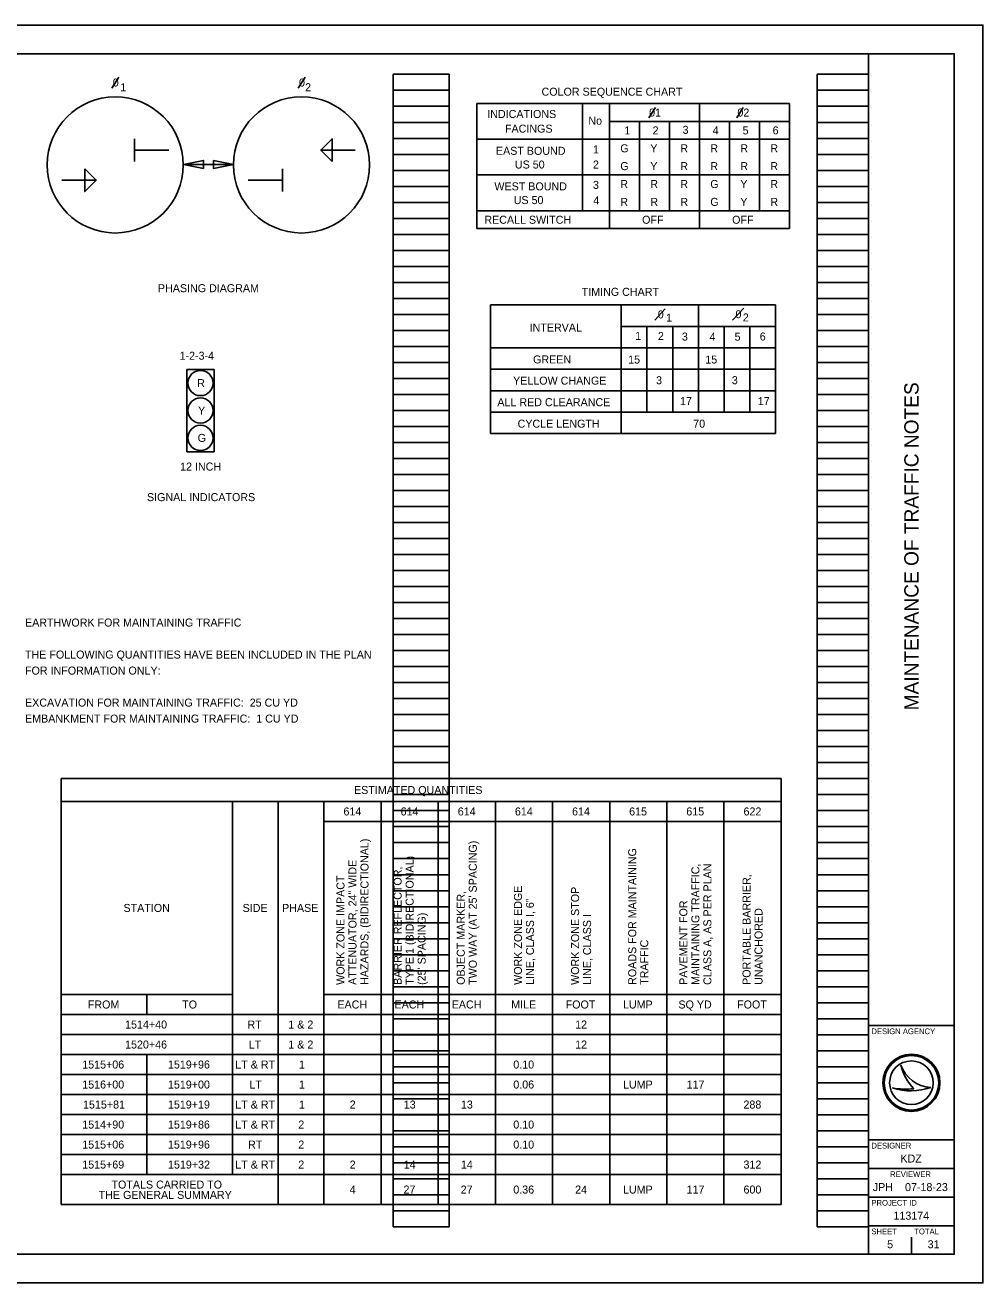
# Model space of a CAD drawing. Extents: x 0 to 34, y 0 to 22.
# Drawn here: x 17.24 to 34, y 0 to 22 of the extents above; entities that cross this region are included whole.
import ezdxf

# ---------------------------------------------------------------- set-up
doc = ezdxf.new("R2010")
doc.units = 0
for name, color, linetype in [('Default', 7, 'Continuous'), ('SG_P_Heads', 7, 'Continuous'), ('SH_Border', 7, 'Continuous'), ('SH_Cut_Line', 7, 'Continuous'), ('SH_Data', 7, 'Continuous'), ('SH_Text', 7, 'Continuous'), ('TX_P_1', 7, 'Continuous'), ('TX_P_20', 7, 'Continuous')]:
    doc.layers.add(name, color=color, linetype=linetype)

msp = doc.modelspace()

# ---------------------------------------------------------------- linework, layer by layer
at = {"layer": 'Default'}
for p, q in [((25.145, 20.629), (25.145, 18.441)), ((25.145, 20.629), (30.615, 20.629)), ((26.996, 20.629), (26.996, 18.754)), ((27.465, 20.629), (27.465, 18.441)), ((29.04, 20.629), (29.04, 18.441)), ((30.615, 20.629), (30.615, 18.441)), ((30.615, 20.629), (30.615, 18.441)), ((27.465, 20.316), (30.615, 20.316)), ((27.99, 20.316), (27.99, 18.754)), ((28.515, 20.316), (28.515, 18.754)), ((29.565, 20.316), (29.565, 18.754)), ((30.09, 20.316), (30.09, 18.754)), ((25.145, 20.004), (30.615, 20.004)), ((25.145, 19.379), (30.615, 19.379)), ((25.145, 18.754), (30.615, 18.754)), ((25.145, 18.441), (30.615, 18.441)), ((25.387, 17.106), (30.373, 17.106)), ((25.387, 17.106), (25.387, 14.856)), ((27.673, 17.106), (27.673, 14.856)), ((29.023, 17.106), (29.023, 15.231)), ((30.373, 17.106), (30.373, 14.856)), ((27.673, 16.731), (30.373, 16.731)), ((28.123, 16.731), (28.123, 15.231)), ((28.573, 16.731), (28.573, 15.231)), ((29.473, 16.731), (29.473, 15.231)), ((29.923, 16.731), (29.923, 15.231)), ((25.387, 16.356), (30.373, 16.356)), ((20.55, 15.976), (20.071, 15.976)), ((20.071, 15.976), (20.071, 14.534)), ((20.55, 14.534), (20.55, 15.976)), ((25.387, 15.981), (30.373, 15.981)), ((25.387, 15.606), (30.373, 15.606)), ((25.387, 15.231), (30.373, 15.231)), ((25.387, 14.856), (30.373, 14.856)), ((20.071, 14.534), (20.55, 14.534))]:
    msp.add_line(p, q, dxfattribs=at)
for centre in [(20.31, 15.739), (20.31, 15.259), (20.31, 14.78)]:
    msp.add_circle(centre, 0.22, dxfattribs=at)
at = {"layer": 'SG_P_Heads'}
for p, q in [((19.154, 20.014), (19.154, 19.614)), ((19.755, 19.814), (19.154, 19.814)), ((23.014, 19.814), (22.414, 19.814)), ((21.744, 19.089), (21.744, 19.489)), ((17.884, 19.289), (18.485, 19.289)), ((21.143, 19.289), (21.744, 19.289))]:
    msp.add_line(p, q, dxfattribs=at)
for points in [[(22.614, 19.614), (22.414, 19.814), (22.614, 20.014)], [(20.362, 19.493), (20.012, 19.563), (20.362, 19.633)], [(20.535, 19.633), (20.885, 19.563), (20.535, 19.493)], [(18.285, 19.489), (18.485, 19.289), (18.285, 19.089)]]:
    msp.add_lwpolyline(points, close=True, dxfattribs=at)
at = {"layer": 'SH_Border'}
for p, q in [((32, 0.5), (32, 21.5)), ((32, 4.5), (33.5, 4.5)), ((32, 2.5), (33.5, 2.5)), ((32, 2), (33.5, 2)), ((32, 1.5), (33.5, 1.5)), ((32, 1), (33.5, 1))]:
    msp.add_line(p, q, dxfattribs=at)
msp.add_lwpolyline([(1.5, 21.5), (33.5, 21.5), (33.5, 0.5), (1.5, 0.5)], close=True, dxfattribs=at)
at = {"layer": 'SH_Cut_Line'}
msp.add_lwpolyline([(0, 0), (34, 0), (34, 22), (0, 22)], close=True, dxfattribs=at)
at = {"layer": 'SH_Data'}
for p, q in [((23.68, 0.98), (23.68, 21.14)), ((23.68, 21.14), (24.66, 21.14)), ((24.66, 0.98), (24.66, 21.14)), ((31.1, 0.98), (31.1, 21.14)), ((31.1, 21.14), (32, 21.14)), ((32, 0.98), (32, 21.14)), ((23.68, 20.86), (24.66, 20.86)), ((31.1, 20.86), (32, 20.86)), ((23.68, 20.58), (24.66, 20.58)), ((31.1, 20.58), (32, 20.58)), ((23.68, 20.3), (24.66, 20.3)), ((31.1, 20.3), (32, 20.3)), ((23.68, 20.02), (24.66, 20.02)), ((31.1, 20.02), (32, 20.02)), ((23.68, 19.74), (24.66, 19.74)), ((31.1, 19.74), (32, 19.74)), ((20.885, 19.563), (20.012, 19.563)), ((23.68, 19.46), (24.66, 19.46)), ((31.1, 19.46), (32, 19.46)), ((23.68, 19.18), (24.66, 19.18)), ((31.1, 19.18), (32, 19.18)), ((23.68, 18.9), (24.66, 18.9)), ((31.1, 18.9), (32, 18.9)), ((23.68, 18.62), (24.66, 18.62)), ((31.1, 18.62), (32, 18.62)), ((23.68, 18.34), (24.66, 18.34)), ((31.1, 18.34), (32, 18.34)), ((23.68, 18.06), (24.66, 18.06)), ((31.1, 18.06), (32, 18.06)), ((23.68, 17.78), (24.66, 17.78)), ((31.1, 17.78), (32, 17.78)), ((23.68, 17.5), (24.66, 17.5)), ((31.1, 17.5), (32, 17.5)), ((23.68, 17.22), (24.66, 17.22)), ((31.1, 17.22), (32, 17.22)), ((23.68, 16.94), (24.66, 16.94)), ((31.1, 16.94), (32, 16.94)), ((23.68, 16.66), (24.66, 16.66)), ((31.1, 16.66), (32, 16.66)), ((23.68, 16.38), (24.66, 16.38)), ((31.1, 16.38), (32, 16.38)), ((23.68, 16.1), (24.66, 16.1)), ((31.1, 16.1), (32, 16.1)), ((23.68, 15.82), (24.66, 15.82)), ((31.1, 15.82), (32, 15.82)), ((23.68, 15.54), (24.66, 15.54)), ((31.1, 15.54), (32, 15.54)), ((23.68, 15.26), (24.66, 15.26)), ((31.1, 15.26), (32, 15.26)), ((23.68, 14.98), (24.66, 14.98)), ((31.1, 14.98), (32, 14.98)), ((23.68, 14.7), (24.66, 14.7)), ((31.1, 14.7), (32, 14.7)), ((23.68, 14.42), (24.66, 14.42)), ((31.1, 14.42), (32, 14.42)), ((23.68, 14.14), (24.66, 14.14)), ((31.1, 14.14), (32, 14.14)), ((23.68, 13.86), (24.66, 13.86)), ((31.1, 13.86), (32, 13.86)), ((23.68, 13.58), (24.66, 13.58)), ((31.1, 13.58), (32, 13.58)), ((23.68, 13.3), (24.66, 13.3)), ((31.1, 13.3), (32, 13.3)), ((23.68, 13.02), (24.66, 13.02)), ((31.1, 13.02), (32, 13.02)), ((23.68, 12.74), (24.66, 12.74)), ((31.1, 12.74), (32, 12.74)), ((23.68, 12.46), (24.66, 12.46)), ((31.1, 12.46), (32, 12.46)), ((23.68, 12.18), (24.66, 12.18)), ((31.1, 12.18), (32, 12.18)), ((23.68, 11.9), (24.66, 11.9)), ((31.1, 11.9), (32, 11.9)), ((23.68, 11.62), (24.66, 11.62)), ((31.1, 11.62), (32, 11.62)), ((23.68, 11.34), (24.66, 11.34)), ((31.1, 11.34), (32, 11.34)), ((23.68, 11.06), (24.66, 11.06)), ((31.1, 11.06), (32, 11.06)), ((23.68, 10.78), (24.66, 10.78)), ((31.1, 10.78), (32, 10.78)), ((23.68, 10.5), (24.66, 10.5)), ((31.1, 10.5), (32, 10.5)), ((23.68, 10.22), (24.66, 10.22)), ((31.1, 10.22), (32, 10.22)), ((23.68, 9.94), (24.66, 9.94)), ((31.1, 9.94), (32, 9.94)), ((23.68, 9.66), (24.66, 9.66)), ((31.1, 9.66), (32, 9.66)), ((23.68, 9.38), (24.66, 9.38)), ((31.1, 9.38), (32, 9.38)), ((23.68, 9.1), (24.66, 9.1)), ((31.1, 9.1), (32, 9.1)), ((23.68, 8.82), (24.66, 8.82)), ((31.1, 8.82), (32, 8.82)), ((23.68, 8.54), (24.66, 8.54)), ((31.1, 8.54), (32, 8.54)), ((23.68, 8.26), (24.66, 8.26)), ((31.1, 8.26), (32, 8.26)), ((23.68, 7.98), (24.66, 7.98)), ((31.1, 7.98), (32, 7.98)), ((23.68, 7.7), (24.66, 7.7)), ((31.1, 7.7), (32, 7.7)), ((23.68, 7.42), (24.66, 7.42)), ((31.1, 7.42), (32, 7.42)), ((23.68, 7.14), (24.66, 7.14)), ((31.1, 7.14), (32, 7.14)), ((23.68, 6.86), (24.66, 6.86)), ((31.1, 6.86), (32, 6.86)), ((23.68, 6.58), (24.66, 6.58)), ((31.1, 6.58), (32, 6.58)), ((23.68, 6.3), (24.66, 6.3)), ((31.1, 6.3), (32, 6.3)), ((23.68, 6.02), (24.66, 6.02)), ((31.1, 6.02), (32, 6.02)), ((23.68, 5.74), (24.66, 5.74)), ((31.1, 5.74), (32, 5.74)), ((23.68, 5.46), (24.66, 5.46)), ((31.1, 5.46), (32, 5.46)), ((23.68, 5.18), (24.66, 5.18)), ((31.1, 5.18), (32, 5.18)), ((23.68, 4.9), (24.66, 4.9)), ((31.1, 4.9), (32, 4.9)), ((23.68, 4.62), (24.66, 4.62)), ((31.1, 4.62), (32, 4.62)), ((23.68, 4.34), (24.66, 4.34)), ((31.1, 4.34), (32, 4.34)), ((23.68, 4.06), (24.66, 4.06)), ((31.1, 4.06), (32, 4.06)), ((23.68, 3.78), (24.66, 3.78)), ((31.1, 3.78), (32, 3.78)), ((32.567, 3.81), (32.567, 3.81)), ((23.68, 3.5), (24.66, 3.5)), ((31.1, 3.5), (32, 3.5)), ((32.417, 3.41), (32.417, 3.41)), ((32.75, 3.5), (32.75, 3.5)), ((33.087, 3.419), (33.087, 3.419)), ((23.68, 3.22), (24.66, 3.22)), ((31.1, 3.22), (32, 3.22)), ((23.68, 2.94), (24.66, 2.94)), ((31.1, 2.94), (32, 2.94)), ((23.68, 2.66), (24.66, 2.66)), ((31.1, 2.66), (32, 2.66)), ((23.68, 2.38), (24.66, 2.38)), ((31.1, 2.38), (32, 2.38)), ((23.68, 2.1), (24.66, 2.1)), ((31.1, 2.1), (32, 2.1)), ((23.68, 1.82), (24.66, 1.82)), ((31.1, 1.82), (32, 1.82)), ((23.68, 1.54), (24.66, 1.54)), ((31.1, 1.54), (32, 1.54)), ((23.68, 1.26), (24.66, 1.26)), ((31.1, 1.26), (32, 1.26)), ((23.68, 0.98), (24.66, 0.98)), ((31.1, 0.98), (32, 0.98)), ((32.375, 0.675), (32.375, 0.675)), ((32.75, 0.5), (32.75, 0.8))]:
    msp.add_line(p, q, dxfattribs=at)
for centre, radius in [((18.819, 19.555), 1.191), ((22.078, 19.555), 1.191), ((32.75, 3.5), 0.5), ((32.75, 3.5), 0.477), ((32.75, 3.5), 0.477), ((32.75, 3.5), 0.382)]:
    msp.add_circle(centre, radius, dxfattribs=at)
for centre, radius, start, end in [((33.116, 3.998), 0.58, 198.9257, 198.9319), ((33.347, 3.97), 0.796, 191.6379, 191.6421), ((33.116, 3.998), 0.58, 198.9319, 267.1657), ((33.347, 3.97), 0.796, 191.6421, 226.0947), ((32.739, 4.37), 1.013, 251.4576, 290.0832), ((32.648, 4.654), 1.266, 259.4964, 259.4995), ((32.739, 4.37), 1.013, 251.4527, 251.4576), ((32.648, 4.654), 1.266, 259.4995, 276.6672)]:
    msp.add_arc(centre, radius, start, end, dxfattribs=at)
at = {"layer": 'TX_P_1'}
for p, q in [((18.883, 21.088), (18.758, 20.895)), ((22.143, 21.088), (22.017, 20.895)), ((28.155, 20.381), (28.27, 20.562)), ((29.693, 20.381), (29.808, 20.562)), ((28.262, 16.837), (28.439, 17.038)), ((29.619, 16.838), (29.819, 17.048))]:
    msp.add_line(p, q, dxfattribs=at)
at = {"layer": 'TX_P_20'}
for p, q in [((17.87, 1.369), (17.87, 8.821)), ((17.87, 8.821), (30.47, 8.821)), ((30.47, 1.369), (30.47, 8.821)), ((17.87, 8.421), (30.47, 8.421)), ((20.87, 1.894), (20.87, 8.421)), ((21.67, 1.369), (21.67, 8.421)), ((22.47, 1.369), (22.47, 8.421)), ((23.47, 1.369), (23.47, 8.421)), ((24.47, 1.369), (24.47, 8.421)), ((25.47, 1.369), (25.47, 8.421)), ((26.47, 1.369), (26.47, 8.421)), ((27.47, 1.369), (27.47, 8.421)), ((28.47, 1.369), (28.47, 8.421)), ((29.47, 1.369), (29.47, 8.421)), ((22.47, 8.071), (30.47, 8.071)), ((17.87, 5.044), (20.87, 5.044)), ((19.37, 4.694), (19.37, 5.044)), ((22.47, 5.044), (30.47, 5.044)), ((17.87, 4.694), (30.47, 4.694)), ((17.87, 4.344), (30.47, 4.344)), ((17.87, 3.994), (30.47, 3.994)), ((19.37, 1.894), (19.37, 3.994)), ((17.87, 3.644), (30.47, 3.644)), ((17.87, 3.294), (30.47, 3.294)), ((17.87, 2.944), (30.47, 2.944)), ((17.87, 2.594), (30.47, 2.594)), ((17.87, 2.244), (30.47, 2.244)), ((17.87, 1.894), (30.47, 1.894)), ((17.87, 1.369), (30.47, 1.369))]:
    msp.add_line(p, q, dxfattribs=at)

# ---------------------------------------------------------------- texts
at = {"layer": 'Default'}
for s, p in [('COLOR SEQUENCE CHART', (26.278, 20.766)), ('TIMING CHART', (26.981, 17.265)), ('R', (20.252, 15.669)), ('Y', (20.268, 15.189)), ('G', (20.261, 14.71)), ('SIGNAL INDICATORS', (19.374, 13.674))]:
    msp.add_text(s, height=0.14, dxfattribs=at).set_placement(p)
at = {"layer": 'SH_Data'}
for s, height, p in [('0', 0.14, (18.775, 20.926)), ('DESIGN AGENCY', 0.1, (32.05, 4.35)), ('DESIGNER', 0.1, (32.05, 2.35)), ('KDZ', 0.14, (32.557, 2.105)), ('REVIEWER', 0.1, (32.378, 1.85)), ('JPH', 0.14, (32.073, 1.605)), ('07-18-23', 0.14, (32.638, 1.605)), ('PROJECT ID', 0.1, (32.05, 1.35)), ('113174', 0.14, (32.436, 1.105)), ('SHEET', 0.1, (32.05, 0.85)), ('TOTAL', 0.1, (32.8, 0.85)), ('5', 0.14, (32.325, 0.605)), ('31', 0.14, (33.034, 0.605))]:
    msp.add_text(s, height=height, dxfattribs=at).set_placement(p)
msp.add_text('MAINTENANCE OF TRAFFIC NOTES', height=0.25, rotation=90, dxfattribs=at).set_placement((32.875, 10.014))
at = {"layer": 'SH_Text'}
for s, p in [('EARTHWORK FOR MAINTAINING TRAFFIC', (17.24, 11.48)), ('THE FOLLOWING QUANTITIES HAVE BEEN INCLUDED IN THE PLAN', (17.24, 10.92)), ('FOR INFORMATION ONLY:', (17.24, 10.64)), ('EXCAVATION FOR MAINTAINING TRAFFIC:  25 CU YD', (17.24, 10.08)), ('EMBANKMENT FOR MAINTAINING TRAFFIC:  1 CU YD', (17.24, 9.8))]:
    msp.add_text(s, height=0.14, dxfattribs=at).set_placement(p)
at = {"layer": 'TX_P_1'}
for s, p in [('1', (18.908, 20.844)), ('0', (22.034, 20.926)), ('2', (22.141, 20.844)), ('INDICATIONS', (25.328, 20.376)), ('01', (28.16, 20.401)), ('02', (29.705, 20.401)), ('FACINGS', (25.638, 20.12)), ('No', (27.097, 20.258)), ('3', (28.746, 20.099)), ('1', (27.727, 20.089)), ('2', (28.221, 20.089)), ('4', (29.271, 20.089)), ('5', (29.796, 20.089)), ('6', (30.321, 20.089)), ('EAST BOUND', (25.48, 19.732)), ('1', (27.178, 19.757)), ('G', (27.656, 19.776)), ('Y', (28.181, 19.776)), ('R', (28.706, 19.776)), ('R', (29.231, 19.776)), ('R', (29.756, 19.776)), ('R', (30.281, 19.776)), ('US 50', (25.812, 19.492)), ('2', (27.178, 19.492)), ('G', (27.656, 19.464)), ('Y', (28.181, 19.464)), ('R', (28.706, 19.464)), ('R', (29.231, 19.464)), ('R', (29.756, 19.464)), ('R', (30.281, 19.464)), ('WEST BOUND', (25.453, 19.11)), ('3', (27.178, 19.136)), ('R', (27.656, 19.151)), ('R', (28.181, 19.151)), ('R', (28.706, 19.151)), ('G', (29.231, 19.151)), ('Y', (29.756, 19.151)), ('R', (30.281, 19.151)), ('US 50', (25.791, 18.87)), ('4', (27.183, 18.863)), ('R', (27.656, 18.839)), ('R', (28.181, 18.839)), ('R', (28.706, 18.839)), ('G', (29.231, 18.839)), ('Y', (29.756, 18.839)), ('R', (30.281, 18.839)), ('RECALL SWITCH', (25.277, 18.526)), ('OFF', (28.038, 18.526)), ('OFF', (29.613, 18.526)), ('PHASING DIAGRAM', (19.565, 17.329)), ('0', (28.312, 16.87)), ('1', (28.457, 16.814)), ('0', (29.671, 16.873)), ('2', (29.799, 16.817)), ('INTERVAL ', (26.069, 16.641)), ('1', (27.916, 16.494)), ('2', (28.314, 16.492)), ('3', (28.734, 16.483)), ('4', (29.217, 16.479)), ('5', (29.656, 16.481)), ('6', (30.096, 16.484)), ('1-2-3-4', (19.944, 16.147)), (' GREEN', (26.078, 16.083)), ('15', (27.794, 16.081)), ('15', (29.144, 16.081)), ('YELLOW CHANGE', (25.78, 15.712)), ('3', (28.282, 15.719)), ('3', (29.607, 15.719)), ('ALL RED CLEARANCE', (25.505, 15.335)), ('17', (28.701, 15.354)), ('17', (30.062, 15.354)), ('CYCLE LENGTH', (25.859, 14.959)), ('70', (28.932, 14.959)), ('12 INCH', (19.954, 14.209))]:
    msp.add_text(s, height=0.14, dxfattribs=at).set_placement(p)
at = {"layer": 'TX_P_20'}
for s, p in [('ESTIMATED QUANTITIES', (22.997, 8.551)), ('614', (22.812, 8.176)), ('614', (23.812, 8.176)), ('614', (24.812, 8.176)), ('614', (25.812, 8.176)), ('614', (26.812, 8.176)), ('615', (27.811, 8.176)), ('615', (28.811, 8.176)), ('622', (29.812, 8.176)), ('STATION', (18.963, 6.488)), ('SIDE', (21.047, 6.488)), ('PHASE', (21.738, 6.488)), ('FROM', (18.339, 4.799)), ('TO', (19.99, 4.799)), ('EACH', (22.706, 4.799)), ('EACH', (23.706, 4.799)), ('EACH', (24.706, 4.799)), ('MILE', (25.747, 4.799)), ('FOOT', (26.7, 4.799)), ('LUMP', (27.703, 4.799)), ('SQ YD', (28.673, 4.799)), ('FOOT', (29.7, 4.799)), ('1514+40', (18.991, 4.449)), ('RT', (21.132, 4.449)), ('1 & 2', (21.847, 4.449)), ('12', (26.866, 4.449)), ('1520+46', (18.991, 4.099)), ('LT', (21.153, 4.099)), ('1 & 2', (21.847, 4.099)), ('12', (26.866, 4.099)), ('1515+06', (18.241, 3.749)), ('1519+96', (19.741, 3.749)), ('LT & RT', (20.919, 3.749)), ('1', (22.034, 3.749)), ('0.10', (25.784, 3.749)), ('1516+00', (18.241, 3.399)), ('1519+00', (19.741, 3.399)), ('LT', (21.165, 3.399)), ('1', (22.034, 3.399)), ('0.06', (25.784, 3.399)), ('LUMP', (27.703, 3.399)), ('117', (28.816, 3.399)), ('1515+81', (18.255, 3.049)), ('1519+19', (19.741, 3.049)), ('LT & RT', (20.919, 3.049)), ('1', (22.034, 3.049)), ('2', (22.921, 3.049)), ('13', (23.867, 3.049)), ('13', (24.867, 3.049)), ('288', (29.811, 3.049)), ('1514+90', (18.241, 2.699)), ('1519+86', (19.741, 2.699)), ('LT & RT', (20.919, 2.699)), ('2', (22.021, 2.699)), ('0.10', (25.784, 2.699)), ('1515+06', (18.241, 2.349)), ('1519+96', (19.741, 2.349)), ('RT', (21.143, 2.349)), ('2', (22.021, 2.349)), ('0.10', (25.784, 2.349)), ('1515+69', (18.241, 1.999)), ('1519+32', (19.742, 1.999)), ('LT & RT', (20.919, 1.999)), ('2', (22.021, 1.999)), ('2', (22.921, 1.999)), ('14', (23.867, 1.999)), ('14', (24.867, 1.999)), ('312', (29.812, 1.999)), ('TOTALS CARRIED TO', (18.753, 1.649)), ('THE GENERAL SUMMARY', (18.528, 1.468)), ('4', (22.92, 1.562)), ('27', (23.863, 1.562)), ('27', (24.863, 1.562)), ('0.36', (25.784, 1.562)), ('24', (26.866, 1.562)), ('LUMP', (27.703, 1.562)), ('117', (28.816, 1.562)), ('600', (29.812, 1.562))]:
    msp.add_text(s, height=0.14, dxfattribs=at).set_placement(p)
for s, p in [('HAZARDS, (BIDIRECTIONAL)', (23.25, 5.212)), ("TWO WAY (AT 25' SPACING)", (25.145, 5.212)), ('ROADS FOR MAINTAINING', (27.935, 5.212)), ('ATTENUATOR, 24" WIDE', (23.04, 5.212)), ('BARRIER REFLECTOR,', (23.83, 5.212)), ('TYPE 1 (BIDIRECTIONAL)', (24.04, 5.212)), ('MAINTAINING TRAFFIC, ', (29.04, 5.212)), ('CLASS A, AS PER PLAN', (29.25, 5.212)), ('WORK ZONE IMPACT', (22.83, 5.212)), ('PORTABLE BARRIER,', (29.935, 5.212)), ('OBJECT MARKER,', (24.935, 5.212)), ('WORK ZONE EDGE', (25.935, 5.212)), ('WORK ZONE STOP', (26.935, 5.212)), ('LINE, CLASS I, 6"', (26.145, 5.212)), ('PAVEMENT FOR', (28.83, 5.212)), ("(25' SPACING)", (24.25, 5.212)), ('LINE, CLASS I', (27.145, 5.212)), ('UNANCHORED', (30.145, 5.212)), ('TRAFFIC', (28.145, 5.212))]:
    msp.add_text(s, height=0.14, rotation=90, dxfattribs=at).set_placement(p)

doc.saveas('drawing.dxf')
